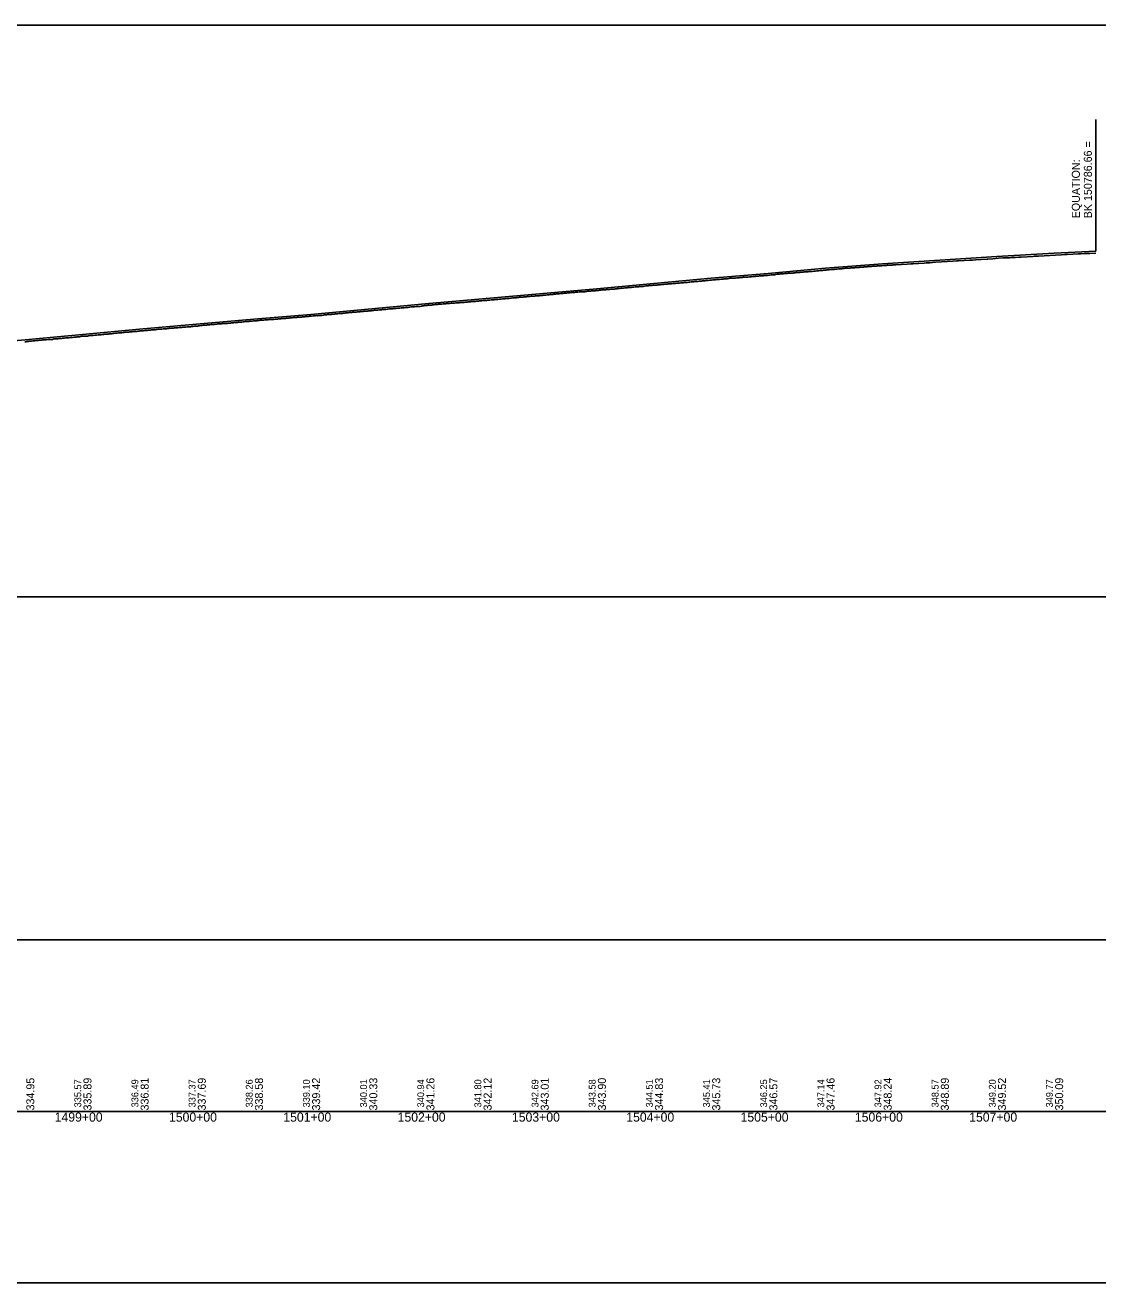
# Model space of a CAD drawing. Extents: x 2898 to 49495, y -15038 to -13538.
# Drawn here: x 39303 to 40242, y -15038 to -13938 of the extents above; entities that cross this region are included whole.
import ezdxf

# ---------------------------------------------------------------- set-up
doc = ezdxf.new("R2010")
doc.units = 0
for name, color, linetype in [('RD_DDB_Profile_EX', 7, 'Continuous'), ('RD_DDB_Profile_PR', 7, 'Continuous'), ('RD_DDB_StaTX', 7, 'Continuous'), ('RD_DDB_StripGrade', 7, 'Continuous'), ('RD_DDB_VCLbl', 7, 'Continuous'), ('RD_GPK_Profile_Cell', 7, 'Continuous'), ('RD_SHT_ShtClip', 7, 'Continuous')]:
    doc.layers.add(name, color=color, linetype=linetype)

msp = doc.modelspace()

# ---------------------------------------------------------------- linework, layer by layer
at = {"layer": 'RD_DDB_Profile_EX'}
for points in [[(40010.8, -14152.1), (40011.8, -14152), (40012.8, -14151.9), (40013.8, -14151.8), (40014.8, -14151.7), (40015.8, -14151.7), (40016.8, -14151.6), (40017.8, -14151.5), (40018.8, -14151.3), (40019.8, -14151.2), (40020.8, -14151.1), (40021.8, -14151.1), (40022.8, -14151), (40023.9, -14150.9), (40024.8, -14150.9), (40025.8, -14150.8), (40026.8, -14150.7), (40027.8, -14150.6), (40028.8, -14150.6), (40029.8, -14150.5), (40030.8, -14150.5), (40031.8, -14150.4), (40032.8, -14150.3), (40033.8, -14150.2), (40034.8, -14150.1), (40035.8, -14150), (40036.8, -14150), (40037.4, -14149.9), (40037.8, -14149.9), (40038.8, -14149.8), (40039.8, -14149.7), (40040.8, -14149.6), (40041.8, -14149.6), (40042.8, -14149.5), (40043.8, -14149.5), (40044.8, -14149.4), (40045.8, -14149.3), (40046.8, -14149.3), (40047.8, -14149.2), (40048.8, -14149.1), (40049.8, -14149.1), (40050.9, -14149), (40051.8, -14148.9), (40052.8, -14148.9), (40053.8, -14148.8), (40054.8, -14148.7), (40055.8, -14148.7), (40056.8, -14148.6), (40057.8, -14148.5), (40058.8, -14148.4), (40059.8, -14148.4), (40060.8, -14148.4), (40061.8, -14148.3), (40062.8, -14148.2), (40063.8, -14148.2), (40064.5, -14148.1), (40064.9, -14148.1), (40069.9, -14147.8), (40074.8, -14147.5), (40078, -14147.3), (40079.8, -14147.2), (40084.8, -14146.8), (40089.8, -14146.5), (40091.5, -14146.4), (40094.8, -14146.2), (40099.8, -14145.9), (40105, -14145.5), (40109.8, -14145.2), (40114.8, -14144.9), (40118.5, -14144.6), (40119.8, -14144.5), (40124.8, -14144.3), (40129.8, -14144), (40132, -14143.9), (40134.8, -14143.7), (40139.8, -14143.3), (40144.8, -14143), (40145.5, -14143), (40149.8, -14142.7), (40154.8, -14142.4), (40159, -14142.1), (40159.8, -14142), (40164.8, -14141.9), (40166.1, -14141.8), (40169.8, -14141.6), (40172.5, -14141.4), (40174.8, -14141.3), (40179.8, -14141), (40184.8, -14140.7), (40186, -14140.6), (40189.8, -14140.4), (40194.8, -14140.1), (40199.8, -14139.8), (40204.8, -14139.5), (40209.8, -14139.3), (40213, -14139.1), (40214.8, -14139.1), (40219.8, -14138.7), (40224.8, -14138.5), (40226.5, -14138.4), (40229.8, -14138.3)], [(40229.8, -14138.3), (40234.8, -14138.1), (40240, -14137.8)], [(39914.9, -14160.4), (39915.9, -14160.3), (39916.9, -14160.2), (39917.9, -14160.2), (39918.9, -14160.1), (39919.9, -14159.9), (39920.9, -14159.9), (39921.9, -14159.8), (39922.9, -14159.7), (39923.9, -14159.8), (39924.9, -14159.7), (39925.9, -14159.5), (39926.9, -14159.5), (39927.9, -14159.4), (39928.9, -14159.3), (39929.4, -14159.3), (39929.9, -14159.2), (39930.9, -14159.1), (39931.9, -14159), (39932.9, -14159), (39933.9, -14158.9), (39934.9, -14158.8), (39935.9, -14158.8), (39936.9, -14158.6), (39937.9, -14158.6), (39938.9, -14158.5), (39939.9, -14158.4), (39940.9, -14158.3), (39941.9, -14158.3), (39942.9, -14158.1), (39943.9, -14158.1), (39944.9, -14158), (39945.9, -14157.8), (39946.9, -14157.8), (39947.9, -14157.7), (39948.9, -14157.6), (39949.9, -14157.5), (39950.9, -14157.4), (39951.9, -14157.4), (39952.9, -14157.3), (39953.9, -14157.2), (39954.9, -14157.1), (39955.9, -14156.9), (39956.4, -14156.9), (39956.9, -14156.8), (39957.9, -14156.8), (39958.9, -14156.7), (39959.9, -14156.6), (39960.9, -14156.4), (39961.9, -14156.4), (39962.9, -14156.2), (39963.9, -14156.1), (39964.9, -14156), (39965.9, -14155.9), (39966.9, -14155.9), (39967.9, -14155.8), (39968.9, -14155.7), (39969.9, -14155.6), (39970.9, -14155.5), (39971.9, -14155.5), (39972.9, -14155.4), (39973.9, -14155.3), (39974.9, -14155.3), (39975.9, -14155.2), (39976.9, -14155), (39977.9, -14154.9), (39978.9, -14154.9), (39979.9, -14154.8), (39980.9, -14154.7), (39981.9, -14154.6), (39982.9, -14154.5), (39983.4, -14154.5), (39983.9, -14154.4), (39984.9, -14154.3), (39985.9, -14154.3), (39986.9, -14154.2), (39987.9, -14154.1), (39988.9, -14154), (39989.9, -14154), (39990.8, -14153.9), (39991.9, -14153.8), (39992.9, -14153.7), (39993.9, -14153.6), (39994.8, -14153.5), (39995.8, -14153.4), (39996.9, -14153.3), (39997.8, -14153.2), (39998.8, -14153.1), (39999.8, -14153.1), (40000.8, -14153), (40001.8, -14152.8), (40002.8, -14152.8), (40003.9, -14152.7), (40004.8, -14152.6), (40005.8, -14152.5), (40006.8, -14152.4), (40007.8, -14152.3), (40008.8, -14152.3), (40009.8, -14152.2), (40010.4, -14152.1), (40010.8, -14152.1)], [(39818.9, -14169.3), (39819.9, -14169.2), (39820.9, -14169.1), (39821.3, -14169), (39821.9, -14168.9), (39822.9, -14168.8), (39823.9, -14168.7), (39824.9, -14168.6), (39825.9, -14168.5), (39826.9, -14168.4), (39827.9, -14168.3), (39828.9, -14168.2), (39829.9, -14168.1), (39830.9, -14168), (39831.9, -14168), (39832.9, -14167.8), (39833.9, -14167.8), (39834.9, -14167.7), (39835.9, -14167.5), (39836.9, -14167.4), (39837.9, -14167.4), (39838.9, -14167.3), (39839.9, -14167.2), (39840.9, -14167), (39841.9, -14167), (39842.9, -14166.9), (39843.9, -14166.9), (39844.9, -14166.8), (39845.9, -14166.6), (39846.9, -14166.5), (39847.9, -14166.4), (39848.4, -14166.4), (39848.9, -14166.3), (39849.9, -14166.2), (39850.9, -14166.2), (39851.9, -14166.1), (39852.9, -14166), (39853.9, -14165.9), (39854.9, -14165.8), (39855.9, -14165.8), (39856.9, -14165.7), (39857.9, -14165.6), (39858.9, -14165.5), (39859.9, -14165.4), (39860.9, -14165.3), (39861.9, -14165.2), (39862.9, -14165.1), (39863.9, -14165), (39864.9, -14164.9), (39865.9, -14164.8), (39866.9, -14164.8), (39867.9, -14164.7), (39868.9, -14164.6), (39869.9, -14164.5), (39870.9, -14164.4), (39871.9, -14164.3), (39872.9, -14164.2), (39873.9, -14164.1), (39874.9, -14164.1), (39875.4, -14164.1), (39875.9, -14164), (39876.9, -14163.9), (39877.9, -14163.8), (39878.9, -14163.7), (39879.9, -14163.6), (39880.9, -14163.5), (39881.9, -14163.5), (39882.9, -14163.4), (39883.9, -14163.3), (39884.9, -14163.2), (39885.9, -14163.1), (39886.9, -14163.1), (39887.9, -14163), (39888.9, -14162.8), (39889.9, -14162.8), (39890.9, -14162.7), (39891.9, -14162.6), (39892.9, -14162.5), (39893.9, -14162.4), (39894.9, -14162.3), (39895.9, -14162.2), (39896.9, -14162.1), (39897.9, -14162), (39898.9, -14161.9), (39899.9, -14161.8), (39900.9, -14161.7), (39901.9, -14161.6), (39902.4, -14161.5), (39902.9, -14161.4), (39903.9, -14161.4), (39904.9, -14161.3), (39905.9, -14161.2), (39906.9, -14161.1), (39907.9, -14161), (39908.9, -14160.9), (39909.9, -14160.8), (39910.9, -14160.8), (39911.9, -14160.7), (39912.9, -14160.6), (39913.9, -14160.5), (39914.9, -14160.4)], [(39625, -14186.5), (39626, -14186.4), (39627, -14186.3), (39628, -14186.2), (39629, -14186.1), (39630, -14186), (39631, -14186), (39632.2, -14185.8), (39633, -14185.8), (39634, -14185.7), (39635, -14185.6), (39636, -14185.5), (39637, -14185.4), (39638, -14185.3), (39639, -14185.2), (39640, -14185.1), (39641, -14184.9), (39642, -14184.8), (39643, -14184.8), (39644, -14184.7), (39645, -14184.6), (39646, -14184.5), (39647, -14184.4), (39648, -14184.4), (39649, -14184.4), (39650, -14184.2), (39651, -14184), (39652, -14183.9), (39653, -14183.8), (39654, -14183.7), (39655, -14183.6), (39656, -14183.5), (39657, -14183.5), (39658, -14183.4), (39659, -14183.3), (39659.3, -14183.2), (39660, -14183.2), (39661, -14183.1), (39662, -14182.9), (39663, -14182.9), (39664, -14182.8), (39665, -14182.6), (39666, -14182.6), (39667, -14182.5), (39668, -14182.4), (39669, -14182.3), (39670, -14182.3), (39671, -14182.2), (39672, -14182), (39673, -14181.9), (39674, -14181.9), (39675, -14181.8), (39676, -14181.7), (39677, -14181.6), (39678, -14181.5), (39679, -14181.5), (39680, -14181.4), (39681, -14181.3), (39682, -14181.3), (39683, -14181.2), (39684, -14181.1), (39685, -14181.1), (39686, -14181), (39686.3, -14180.9), (39687, -14180.9), (39688, -14180.8), (39689, -14180.6), (39690, -14180.6), (39690.9, -14180.5), (39691.9, -14180.4), (39692.9, -14180.4), (39693.9, -14180.3), (39694.9, -14180.2), (39695.9, -14180.1), (39696.9, -14180.1), (39697.9, -14180), (39698.9, -14179.9), (39699.9, -14179.8), (39700.9, -14179.7), (39701.9, -14179.6), (39702.9, -14179.5), (39703.9, -14179.4), (39704.9, -14179.4), (39705.9, -14179.3), (39706.9, -14179.2), (39707.9, -14179.1), (39708.9, -14178.9), (39709.9, -14178.9), (39710.9, -14178.8), (39711.9, -14178.7), (39712.9, -14178.6), (39713.3, -14178.6), (39713.9, -14178.5), (39714.9, -14178.4), (39715.9, -14178.3), (39716.9, -14178.3), (39717.9, -14178.2), (39718.9, -14178.1), (39719.9, -14178), (39720.9, -14177.9), (39721.9, -14177.8)], [(39721.9, -14177.8), (39722.9, -14177.7), (39723.9, -14177.6), (39724.9, -14177.5), (39725.9, -14177.4), (39726.9, -14177.4), (39727.9, -14177.3), (39728.9, -14177.2), (39729.9, -14177.1), (39730.9, -14177), (39731.9, -14176.9), (39732.9, -14176.9), (39733.9, -14176.8), (39734.9, -14176.7), (39735.9, -14176.5), (39736.9, -14176.4), (39737.9, -14176.4), (39738.9, -14176.3), (39739.9, -14176.2), (39740.3, -14176.2), (39740.9, -14176.1), (39741.9, -14176), (39742.9, -14175.9), (39743.9, -14175.8), (39744.9, -14175.7), (39745.9, -14175.6), (39746.9, -14175.6), (39747.9, -14175.5), (39748.9, -14175.4), (39749.9, -14175.3), (39750.9, -14175.3), (39751.9, -14175.2), (39752.9, -14175.1), (39753.9, -14175), (39754.9, -14174.9), (39755.9, -14174.8), (39756.9, -14174.7), (39757.9, -14174.6), (39758.9, -14174.5), (39759.9, -14174.4), (39760.9, -14174.3), (39761.9, -14174.2), (39762.9, -14174.1), (39763.9, -14174), (39764.9, -14173.9), (39765.9, -14173.8), (39766.9, -14173.7), (39767.3, -14173.7), (39767.9, -14173.6), (39768.9, -14173.5), (39769.9, -14173.5), (39770.9, -14173.4), (39771.9, -14173.3), (39772.9, -14173.2), (39773.9, -14173.1), (39774.9, -14173), (39775.9, -14173), (39776.9, -14172.8), (39777.9, -14172.7), (39778.9, -14172.6), (39779.9, -14172.5), (39780.9, -14172.4), (39781.9, -14172.4), (39782.9, -14172.3), (39783.9, -14172.2), (39784.9, -14172), (39785.9, -14171.9), (39786.9, -14171.9), (39787.9, -14171.8), (39788.9, -14171.7), (39789.9, -14171.6), (39790.9, -14171.6), (39791.9, -14171.6), (39792.9, -14171.6), (39793.9, -14171.3), (39794.3, -14171.3), (39794.9, -14171.2), (39795.9, -14171.2), (39796.9, -14171.1), (39797.9, -14171), (39798.9, -14170.9), (39799.9, -14170.8), (39800.9, -14170.7), (39801.9, -14170.7), (39802.9, -14170.6), (39803.9, -14170.5), (39804.9, -14170.4), (39805.9, -14170.3), (39806.9, -14170.2), (39807.9, -14170.1), (39808.9, -14170.1), (39809.9, -14170), (39810.9, -14169.9), (39811.9, -14169.8), (39812.9, -14169.8), (39813.9, -14169.7), (39814.9, -14169.6), (39815.9, -14169.5), (39816.9, -14169.4), (39817.9, -14169.3), (39818.9, -14169.3)], [(39525, -14195.4), (39526, -14195.3), (39527, -14195.2), (39528, -14195.1), (39529, -14195.1), (39530, -14195), (39531, -14194.9), (39532, -14194.8), (39533, -14194.7), (39534, -14194.6), (39535, -14194.5), (39536, -14194.5), (39537, -14194.4), (39538, -14194.3), (39539, -14194.2), (39540, -14194.2), (39541, -14194.1), (39542, -14194), (39543, -14194), (39544, -14193.8), (39545, -14193.8), (39546, -14193.7), (39547, -14193.6), (39548, -14193.5), (39549, -14193.4), (39550, -14193.3), (39551.2, -14193.2), (39552, -14193.1), (39553, -14193), (39554, -14192.9), (39555, -14192.8), (39556, -14192.8), (39557, -14192.7), (39558, -14192.5), (39559, -14192.6), (39560, -14192.4), (39561, -14192.3), (39562, -14192.3), (39563, -14192.3), (39564, -14192), (39565, -14191.9), (39566, -14191.8), (39567, -14191.7), (39568, -14191.6), (39569, -14191.5), (39570, -14191.5), (39571, -14191.4), (39572, -14191.3), (39573, -14191.2), (39574, -14191.1), (39575, -14191), (39576, -14191), (39577, -14190.9), (39578.2, -14190.7), (39579, -14190.7), (39580, -14190.6), (39581, -14190.6), (39582, -14190.4), (39583, -14190.3), (39584, -14190.2), (39585, -14190.1), (39586, -14190), (39587, -14189.9), (39588, -14189.9), (39589, -14189.8), (39590, -14189.6), (39591, -14189.6), (39592, -14189.5), (39593, -14189.5), (39594, -14189.3), (39595, -14189.3), (39596, -14189.1), (39597, -14189), (39598, -14188.9), (39599, -14188.8), (39600, -14188.7), (39601, -14188.7), (39602, -14188.5), (39603, -14188.5), (39604, -14188.4), (39605.2, -14188.3), (39606, -14188.3), (39607, -14188.1), (39608, -14187.9), (39609, -14187.8), (39610, -14187.8), (39611, -14187.7), (39612, -14187.6), (39613, -14187.5), (39614, -14187.5), (39615, -14187.4), (39616, -14187.3), (39617, -14187.2), (39618, -14187.2), (39619, -14187.1), (39620, -14187), (39621, -14186.8), (39622, -14186.7), (39623, -14186.6), (39624, -14186.5), (39625, -14186.5)], [(39425, -14204.1), (39426, -14204.1), (39427, -14204), (39428, -14203.8), (39429, -14203.7), (39430, -14203.6), (39431, -14203.5), (39432, -14203.5), (39433, -14203.4), (39434, -14203.3), (39435, -14203.2), (39436, -14203.2), (39437, -14203.1), (39438, -14203), (39439, -14202.9), (39440, -14202.8), (39441, -14202.7), (39442, -14202.7), (39443.2, -14202.6), (39444, -14202.5), (39445, -14202.4), (39446, -14202.3), (39447, -14202.2), (39448, -14202.2), (39449, -14202.1), (39450, -14201.9), (39451, -14201.7), (39452, -14201.7), (39453, -14201.6), (39454, -14201.6), (39455, -14201.4), (39456, -14201.3), (39457, -14201.2), (39458, -14201.2), (39459, -14201), (39460, -14201), (39461, -14200.8), (39462, -14200.8), (39463, -14200.7), (39464, -14200.6), (39465, -14200.5), (39466, -14200.4), (39467, -14200.4), (39468, -14200.3), (39469, -14200.2), (39470.2, -14200.1), (39471, -14200), (39472, -14199.8), (39473, -14199.7), (39474, -14199.7), (39475, -14199.6), (39476, -14199.5), (39477, -14199.4), (39478, -14199.3), (39479, -14199.3), (39480, -14199.3), (39481, -14199.1), (39482, -14199.1), (39483, -14199.1), (39484, -14198.8), (39485, -14198.8), (39486, -14198.7), (39487, -14198.6), (39488, -14198.5), (39489, -14198.4), (39490, -14198.3), (39491, -14198.2), (39492, -14198.2), (39493, -14198.1), (39494, -14198), (39495, -14197.9), (39496, -14197.8), (39497.2, -14197.7), (39498, -14197.6), (39499, -14197.6), (39500, -14197.4), (39501, -14197.4), (39502, -14197.3), (39503, -14197.2), (39504, -14197.1), (39505, -14197), (39506, -14197), (39507, -14196.9), (39508, -14196.7), (39509, -14196.6), (39510, -14196.6), (39511, -14196.5), (39512, -14196.5), (39513, -14196.3), (39514, -14196.3), (39515, -14196.2), (39516, -14196.1), (39517, -14196), (39518, -14195.9), (39519, -14195.9), (39520, -14195.8), (39521, -14195.8), (39522, -14195.7), (39523, -14195.6), (39524.2, -14195.5), (39525, -14195.4)], [(39324.9, -14213.4), (39325.9, -14213.3), (39327.2, -14213.3), (39327.9, -14213.1), (39328.9, -14212.9), (39330.2, -14212.8), (39330.9, -14212.8), (39331.9, -14212.7), (39332.9, -14212.6), (39334.2, -14212.5), (39335.1, -14212.4), (39335.9, -14212.3), (39336.9, -14212.2), (39337.9, -14212.1), (39338.9, -14211.9), (39340.2, -14211.9), (39340.9, -14211.8), (39341.9, -14211.8), (39342.9, -14211.7), (39344.2, -14211.7), (39344.9, -14211.6), (39345.9, -14211.5), (39347.2, -14211.3), (39347.9, -14211.3), (39348.9, -14211.1), (39350.2, -14211), (39350.9, -14211), (39351.9, -14210.9), (39352.9, -14210.6), (39353.9, -14210.6), (39354.9, -14210.5), (39355.9, -14210.5), (39357.2, -14210.4), (39357.9, -14210.4), (39358.9, -14210.2), (39359.9, -14210), (39361.2, -14210), (39362.1, -14209.9), (39362.9, -14209.8), (39364.2, -14209.7), (39364.9, -14209.6), (39365.9, -14209.5), (39367.2, -14209.4), (39367.9, -14209.2), (39368.9, -14209.2), (39369.9, -14209.2), (39371.2, -14209.1), (39371.9, -14208.9), (39372.9, -14208.8), (39374.2, -14208.8), (39374.9, -14208.8), (39375.9, -14208.7), (39376.9, -14208.5), (39377.9, -14208.3), (39378.9, -14208.3), (39380, -14208.2), (39381, -14208.1), (39382, -14208), (39383, -14207.9), (39384, -14207.8), (39385, -14207.7), (39386, -14207.6), (39387, -14207.6), (39388, -14207.5), (39389.1, -14207.4), (39390, -14207.3), (39391, -14207.1), (39392, -14207), (39393, -14207), (39394, -14206.9), (39395, -14206.8), (39396, -14206.7), (39397, -14206.6), (39398, -14206.5), (39399, -14206.4), (39400, -14206.4), (39401, -14206.3), (39402, -14206.1), (39403, -14206.1), (39404, -14205.9), (39405, -14205.9), (39406, -14205.8), (39407, -14205.7), (39408, -14205.5), (39409, -14205.5), (39410, -14205.4), (39411, -14205.3), (39412, -14205.2), (39413, -14205.2), (39414, -14205), (39415, -14205), (39416.1, -14204.9), (39417, -14204.8), (39418, -14204.7), (39419, -14204.6), (39420, -14204.5), (39421, -14204.4), (39422, -14204.4), (39423, -14204.3), (39424, -14204.2), (39425, -14204.1)], [(39303.2, -14215.3), (39303.9, -14215.3), (39304.9, -14215.2), (39305.9, -14215.1), (39306.9, -14215), (39308.1, -14214.9), (39308.9, -14214.8), (39310.2, -14214.7), (39310.9, -14214.6), (39311.9, -14214.5), (39312.9, -14214.4), (39313.9, -14214.3), (39314.9, -14214.3), (39315.9, -14214.1), (39317.2, -14214), (39317.9, -14213.9), (39318.9, -14213.8), (39320.2, -14213.7), (39320.9, -14213.6), (39321.9, -14213.6), (39323.2, -14213.5), (39323.9, -14213.4), (39324.9, -14213.4)]]:
    msp.add_lwpolyline(points, dxfattribs=at)
at = {"layer": 'RD_DDB_Profile_PR'}
for points in [[(39253.4, -14218.1), (39303.4, -14213.7), (39353.4, -14209), (39403.4, -14204.4), (39453.4, -14200), (39503.4, -14195.6), (39553.4, -14191.4), (39603.4, -14186.8), (39653.4, -14182.2), (39703.4, -14177.9), (39753.4, -14173.4), (39803.4, -14169), (39853.4, -14164.3), (39903.4, -14159.8), (39953.4, -14155.6), (40003.4, -14151.1), (40053.4, -14147.3), (40103.4, -14144), (40153.4, -14140.9)], [(40153.4, -14140.9), (40203.4, -14138), (40240, -14136.2)]]:
    msp.add_lwpolyline(points, dxfattribs=at)
at = {"layer": 'RD_DDB_VCLbl'}
for p, q in [((40240, -14136.2), (40240, -14021)), ((40240, -14137.8), (40240, -14137.8))]:
    msp.add_line(p, q, dxfattribs=at)
at = {"layer": 'RD_GPK_Profile_Cell'}
msp.add_line((2976.1, -14888.5), (48721.1, -14888.5), dxfattribs=at)
at = {"layer": 'RD_SHT_ShtClip'}
for points in [[(38975.4, -13938.5), (38975.4, -14438.5), (40475.4, -14438.5), (40475.4, -14438.5), (40475.4, -13938.5), (40475.4, -13938.5)], [(38955.4, -14738.5), (40495.4, -14738.5), (40495.4, -15038.5), (38955.4, -15038.5)]]:
    msp.add_lwpolyline(points, close=True, dxfattribs=at)

# ---------------------------------------------------------------- texts
at = {"layer": 'RD_DDB_Profile_PR'}
for s, p in [('BK 150786.66 =', (40236.5, -14107.4)), ('EQUATION:', (40226, -14107.4))]:
    msp.add_text(s, height=7, rotation=90, dxfattribs=at).set_placement(p)
at = {"layer": 'RD_DDB_StaTX'}
for s, p in [('1499+00', (39329.2, -14897.5)), ('1500+00', (39429.2, -14897.5)), ('1501+00', (39529.2, -14897.5)), ('1502+00', (39629.2, -14897.5)), ('1503+00', (39729.2, -14897.5)), ('1504+00', (39829.2, -14897.5)), ('1505+00', (39929.2, -14897.5)), ('1506+00', (40029.2, -14897.5)), ('1507+00', (40129.2, -14897.5))]:
    msp.add_text(s, height=8, dxfattribs=at).set_placement(p)
at = {"layer": 'RD_DDB_StripGrade'}
for s, height, p in [('334.95', 7, (39311.4, -14887.7)), ('335.57', 6, (39352.4, -14885)), ('335.89', 7, (39361.4, -14887.7)), ('336.49', 6, (39402.4, -14885)), ('336.81', 7, (39411.4, -14887.7)), ('337.37', 6, (39452.4, -14885)), ('337.69', 7, (39461.4, -14887.7)), ('338.26', 6, (39502.4, -14885)), ('338.58', 7, (39511.4, -14887.7)), ('339.10', 6, (39552.4, -14885)), ('339.42', 7, (39561.4, -14887.7)), ('340.01', 6, (39602.4, -14885)), ('340.33', 7, (39611.4, -14887.7)), ('340.94', 6, (39652.4, -14885)), ('341.26', 7, (39661.4, -14887.7)), ('341.80', 6, (39702.4, -14885)), ('342.12', 7, (39711.4, -14887.7)), ('342.69', 6, (39752.4, -14885)), ('343.01', 7, (39761.4, -14887.7)), ('343.58', 6, (39802.4, -14885)), ('343.90', 7, (39811.4, -14887.7)), ('344.51', 6, (39852.4, -14885)), ('344.83', 7, (39861.4, -14887.7)), ('345.41', 6, (39902.4, -14885)), ('345.73', 7, (39911.4, -14887.7)), ('346.25', 6, (39952.4, -14885)), ('346.57', 7, (39961.4, -14887.7)), ('347.14', 6, (40002.4, -14885)), ('347.46', 7, (40011.4, -14887.7)), ('347.92', 6, (40052.4, -14885)), ('348.24', 7, (40061.4, -14887.7)), ('348.57', 6, (40102.4, -14885)), ('348.89', 7, (40111.4, -14887.7)), ('349.20', 6, (40152.4, -14885)), ('349.52', 7, (40161.4, -14887.7)), ('349.77', 6, (40202.4, -14885)), ('350.09', 7, (40211.4, -14887.7))]:
    msp.add_text(s, height=height, rotation=90, dxfattribs=at).set_placement(p)

doc.saveas('drawing.dxf')
